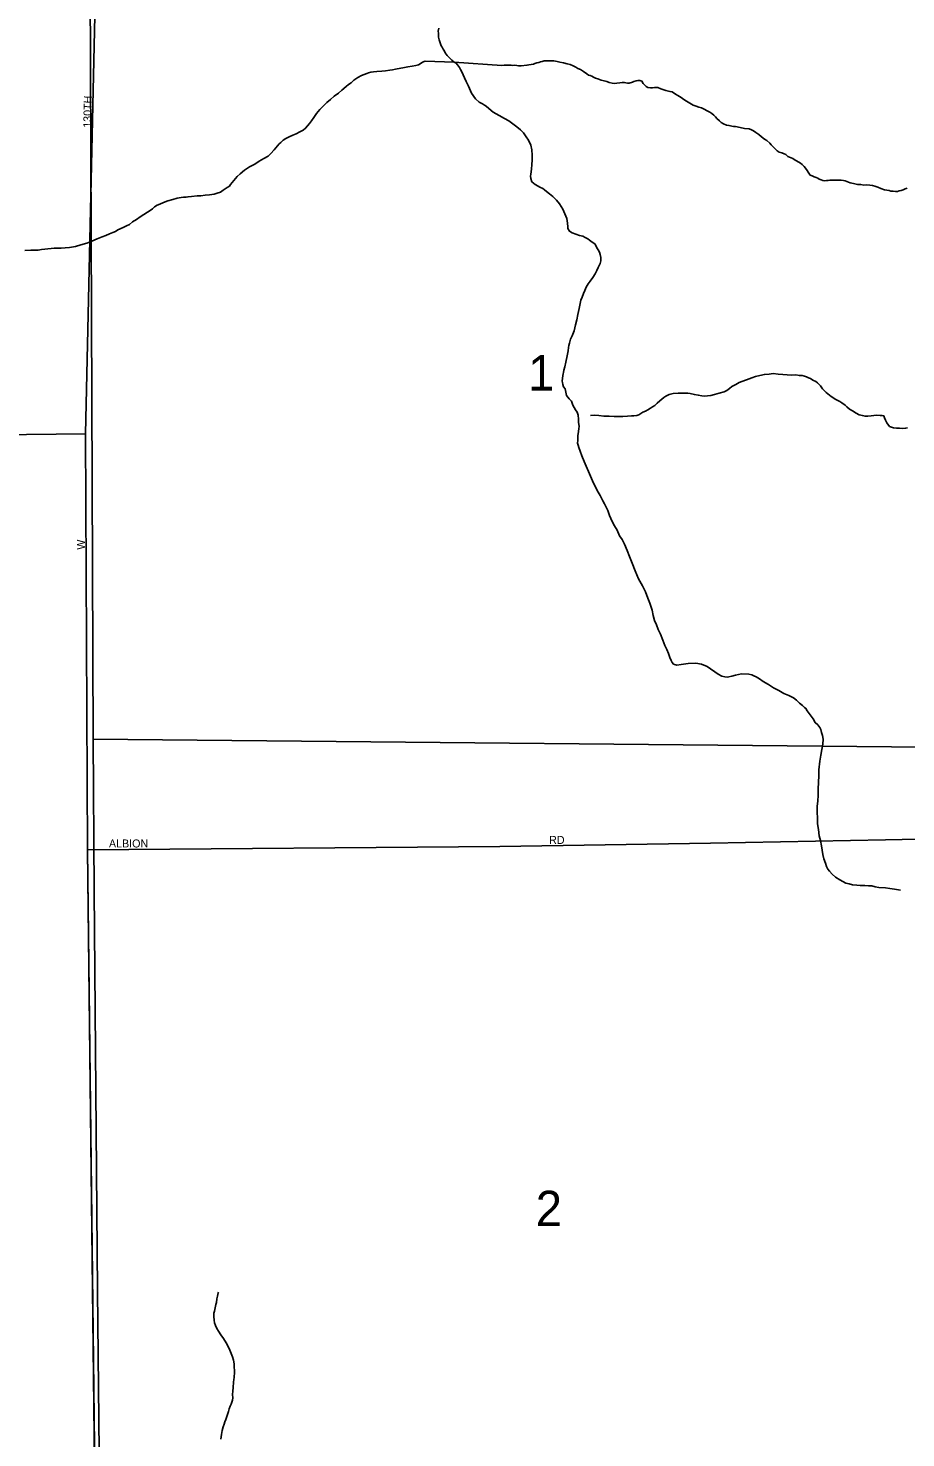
# Model space of a CAD drawing. Extents: x 2010165 to 2382125, y 1060529 to 1407316.
# Drawn here: x 2164475 to 2169958, y 1212363 to 1221171 of the extents above; entities that cross this region are included whole.
import ezdxf

# ---------------------------------------------------------------- set-up
doc = ezdxf.new("R2010")
doc.units = 0
for name, color, linetype in [('GM_X_City_Street', 7, 'Continuous'), ('GM_X_City_Street_Text', 7, 'Continuous'), ('GM_X_Corporation', 7, 'Continuous'), ('GM_X_Minor_River', 7, 'Continuous'), ('GM_X_Section', 7, 'Continuous'), ('GM_X_Section_Text', 7, 'Continuous')]:
    doc.layers.add(name, color=color, linetype=linetype)

msp = doc.modelspace()

# ---------------------------------------------------------------- linework, layer by layer
at = {"layer": 'GM_X_City_Street'}
for points in [[(2164931.2, 1207965.8), (2164930.1, 1208081.5), (2164898.5, 1211429), (2164897.7, 1211462), (2164844.7, 1216037.6), (2164832.8, 1218637), (2164895.8, 1221436.7)], [(2156588.9, 1218553.8), (2158477.6, 1218575.9), (2160599.4, 1218587.6), (2164832.8, 1218637)], [(2164844.7, 1216037.6), (2167420.4, 1216057.6), (2168738.1, 1216077.8), (2169831.9, 1216100.1), (2172347.5, 1216149.6)]]:
    msp.add_lwpolyline(points, dxfattribs=at)
at = {"layer": 'GM_X_Corporation'}
for points in [[(2186878.7, 1221701), (2186923.4, 1220744.1), (2186933.5, 1220238.7), (2186941.3, 1219753.4), (2186978.3, 1216841.2), (2187013.9, 1213879), (2187027.1, 1208132.6), (2187205, 1194725.9), (2177123.5, 1194567.9), (2176176.5, 1194580.3), (2174206.9, 1194531), (2167776.4, 1194381.4), (2165054.7, 1194304.8), (2164968.9, 1199659.4), (2164935.2, 1207756.2), (2164931.8, 1207897.8), (2164930.1, 1208081.5), (2164898.5, 1211429), (2164844.7, 1216037.6), (2164832.8, 1218637), (2164895.8, 1221436.7)], [(2164895.8, 1221436.7), (2164832.8, 1218637), (2164844.7, 1216037.6), (2164898.5, 1211429), (2164930.1, 1208081.5), (2164931.8, 1207897.8), (2164935.2, 1207756.2), (2164968.9, 1199659.4), (2165054.7, 1194304.8), (2162687.3, 1194296.8), (2162163.4, 1194282.6), (2161645.6, 1194276.5), (2161453.7, 1194270.4), (2159224.5, 1194187.1), (2158831.1, 1194172.4), (2158006.9, 1194141.9), (2154020.1, 1193994.5), (2151351.3, 1193919.5)]]:
    msp.add_lwpolyline(points, dxfattribs=at)
at = {"layer": 'GM_X_Minor_River'}
for points in [[(2167040.7, 1221172), (2167037, 1221151.9), (2167037.1, 1221139.9), (2167037.2, 1221129.8), (2167037.4, 1221115.8), (2167041.7, 1221097.8), (2167047.9, 1221079.8), (2167054.2, 1221061.8), (2167060.3, 1221051.9), (2167066.5, 1221039.9), (2167074.6, 1221028), (2167080.8, 1221018), (2167093, 1221000.1), (2167109.3, 1220984.2), (2167121.4, 1220972.3), (2167135.7, 1220958.5), (2167147.7, 1220952.6), (2167155.9, 1220942.7), (2167170.2, 1220924.8), (2167176.3, 1220912.8), (2167182.5, 1220902.9), (2167211.3, 1220839), (2167225.8, 1220809.1), (2167244.4, 1220765.2), (2167268.9, 1220729.4), (2167293.2, 1220709.6), (2167313.4, 1220697.8), (2167325.5, 1220689.9), (2167335.6, 1220684), (2167351.8, 1220670.2), (2167380.1, 1220646.4), (2167416.5, 1220624.8), (2167450.8, 1220607.2), (2167477, 1220591.4), (2167503.3, 1220573.7), (2167527.6, 1220553.9), (2167549.9, 1220536.2), (2167568.2, 1220516.3), (2167586.5, 1220492.5), (2167600.8, 1220470.6), (2167615.2, 1220440.7), (2167621.6, 1220410.6), (2167624.1, 1220378.6), (2167622.5, 1220348.4), (2167620.8, 1220318.3), (2167619.2, 1220292.2), (2167617.4, 1220274.1), (2167615.6, 1220258.1), (2167613.8, 1220246), (2167616, 1220232), (2167622.2, 1220212), (2167642.5, 1220194.2), (2167660.7, 1220184.4), (2167670.8, 1220178.5), (2167690.9, 1220168.7), (2167701, 1220160.8), (2167713.2, 1220150.9), (2167731.4, 1220137.1), (2167751.7, 1220119.3), (2167776, 1220097.5), (2167794.3, 1220073.6), (2167814.8, 1220039.8), (2167827.2, 1220011.8), (2167839.6, 1219981.9), (2167844, 1219951.9), (2167846.3, 1219929.8), (2167846.4, 1219919.8), (2167856.7, 1219901.9), (2167872.8, 1219892), (2167897, 1219884.3), (2167919.1, 1219876.5), (2167939.2, 1219870.8), (2167955.4, 1219862.9), (2167971.5, 1219855.1), (2167981.6, 1219847.2), (2167997.8, 1219833.4), (2168014, 1219823.5), (2168022.1, 1219813.6), (2168028.3, 1219799.6), (2168036.5, 1219785.7), (2168044.7, 1219771.7), (2168048.9, 1219757.7), (2168053.2, 1219737.7), (2168051.4, 1219717.6), (2168047.6, 1219701.5)], [(2166052.3, 1220457.6), (2166068.1, 1220471.9), (2166084, 1220482.1), (2166105.9, 1220492.4), (2166127.8, 1220502.7), (2166147.8, 1220511), (2166171.6, 1220523.3), (2166193.5, 1220533.6), (2166207.4, 1220545.8), (2166219.2, 1220560), (2166233.1, 1220576.2), (2166244.9, 1220592.4), (2166258.6, 1220612.7), (2166276.3, 1220637), (2166296, 1220663.3), (2166319.8, 1220685.6), (2166339.5, 1220706), (2166363.3, 1220726.3), (2166387.1, 1220746.7), (2166412.9, 1220765), (2166434.7, 1220783.4), (2166460.5, 1220805.8), (2166476.3, 1220820), (2166492.2, 1220830.2), (2166510, 1220846.5), (2166533.8, 1220862.8), (2166557.7, 1220875.2), (2166573.7, 1220881.4), (2166589.6, 1220887.6), (2166601.6, 1220891.8), (2166615.6, 1220895.9), (2166631.6, 1220898.1), (2166653.6, 1220900.4), (2166683.6, 1220902.8), (2166707.6, 1220905.1), (2166733.6, 1220909.4), (2166751.6, 1220911.6), (2166769.6, 1220915.9), (2166825.5, 1220924.6), (2166847.5, 1220928.9), (2166873.5, 1220933.2), (2166895.5, 1220937.5), (2166913.5, 1220941.7), (2166923.4, 1220947.9), (2166937.3, 1220958.1), (2166955.3, 1220964.3), (2167135, 1220959.1)], [(2167135, 1220959.1), (2167434.4, 1220938.1), (2167448.4, 1220940.2), (2167466.5, 1220940.4), (2167478.5, 1220940.6), (2167490.5, 1220940.8), (2167500.5, 1220938.9), (2167512.6, 1220939), (2167526.6, 1220937.2), (2167538.7, 1220935.3), (2167554.7, 1220935.5), (2167590.7, 1220940), (2167602.7, 1220942.1), (2167616.7, 1220944.3), (2167630.7, 1220946.5), (2167640.6, 1220950.6), (2167652.6, 1220954.8), (2167664.6, 1220956.9), (2167674.6, 1220961.1), (2167686.6, 1220963.2), (2167698.5, 1220967.4), (2167712.5, 1220967.5), (2167722.6, 1220967.7), (2167736.6, 1220967.8), (2167758.6, 1220966.1), (2167778.7, 1220962.3), (2167796.8, 1220958.5), (2167818.9, 1220954.8), (2167841, 1220949.1), (2167861.1, 1220943.3), (2167879.3, 1220935.5), (2167895.4, 1220927.6), (2167909.5, 1220919.8), (2167925.6, 1220912), (2167943.8, 1220900.1), (2167964, 1220886.3), (2167976.2, 1220878.5), (2167986.2, 1220874.6), (2167996.3, 1220870.7), (2168006.4, 1220864.8), (2168018.5, 1220858.9), (2168032.6, 1220855.1), (2168044.6, 1220851.2), (2168054.7, 1220847.3), (2168072.8, 1220841.5), (2168088.9, 1220837.7), (2168105, 1220831.9), (2168123.1, 1220828.1), (2168137.1, 1220826.3), (2168153.1, 1220828.5), (2168171.2, 1220828.7), (2168185.2, 1220830.9), (2168199.2, 1220831), (2168209.2, 1220829.1), (2168219.3, 1220827.3), (2168229.3, 1220827.4), (2168249.2, 1220833.7), (2168259.2, 1220837.8), (2168273.2, 1220842), (2168283.2, 1220844.1), (2168295.2, 1220844.2), (2168309.2, 1220840.4), (2168317.4, 1220826.5), (2168335.7, 1220806.6), (2168345.8, 1220800.7), (2168361.9, 1220798.9), (2168375.9, 1220799.1), (2168387.9, 1220801.2), (2168408, 1220799.5), (2168428.1, 1220791.7), (2168458.3, 1220782), (2168484.4, 1220776.3), (2168498.5, 1220772.5), (2168518.7, 1220758.7), (2168532.8, 1220750.8), (2168542.9, 1220744.9), (2168555, 1220737.1), (2168571.2, 1220725.2), (2168587.4, 1220715.4), (2168629.8, 1220689.8), (2168647.9, 1220684), (2168664, 1220678.2), (2168682.1, 1220672.4), (2168698.2, 1220664.6), (2168716.4, 1220654.8), (2168732.5, 1220646.9), (2168746.7, 1220637.1), (2168758.8, 1220627.2), (2168769, 1220617.3), (2168777.1, 1220607.4), (2168793.3, 1220591.5), (2168803.5, 1220581.6), (2168819.6, 1220573.8), (2168837.7, 1220566), (2168853.8, 1220562.1), (2168869.9, 1220558.3)], [(2168869.9, 1220558.3), (2168881.9, 1220556.5), (2168894, 1220556.6), (2168922.1, 1220550.9), (2168950.2, 1220545.3), (2168978.3, 1220541.6), (2168994.4, 1220535.8), (2169006.5, 1220529.9), (2169020.7, 1220520), (2169038.9, 1220506.2), (2169057.1, 1220492.4), (2169075.3, 1220478.6), (2169089.5, 1220468.7), (2169107.7, 1220452.9), (2169115.8, 1220442.9), (2169130, 1220429.1), (2169140.2, 1220419.2), (2169154.4, 1220405.3), (2169166.5, 1220397.4), (2169182.6, 1220391.6), (2169198.7, 1220385.8), (2169208.8, 1220381.9), (2169221, 1220370), (2169241.1, 1220360.2), (2169251.2, 1220356.3), (2169261.3, 1220350.4), (2169299.7, 1220326.8), (2169309.8, 1220318.9), (2169322, 1220307), (2169332.1, 1220297.1), (2169342.4, 1220281.2), (2169348.5, 1220271.2), (2169360.7, 1220253.3), (2169372.8, 1220247.5), (2169384.9, 1220241.6), (2169397, 1220237.7), (2169407.1, 1220233.8), (2169417.2, 1220227.9), (2169429.2, 1220224.1), (2169439.3, 1220220.2), (2169451.4, 1220218.3), (2169461.4, 1220218.4), (2169471.4, 1220218.6), (2169483.4, 1220220.7), (2169493.4, 1220220.8), (2169513.4, 1220221.1), (2169525.4, 1220221.2), (2169537.5, 1220221.4), (2169553.5, 1220221.6), (2169567.5, 1220219.7), (2169579.6, 1220217.9), (2169589.7, 1220214), (2169609.8, 1220204.2), (2169631.9, 1220200.5), (2169656, 1220194.7), (2169676.1, 1220195), (2169696.1, 1220191.2), (2169714.2, 1220191.4), (2169732.2, 1220189.6), (2169750.3, 1220187.9), (2169764.4, 1220184), (2169782.5, 1220178.2), (2169802.6, 1220170.4), (2169824.8, 1220160.7), (2169852.9, 1220157), (2169864.9, 1220153.1), (2169879, 1220153.3), (2169893, 1220151.5), (2169905, 1220151.6), (2169917, 1220153.8), (2169929, 1220157.9), (2169941, 1220160.1), (2169952.9, 1220168.3), (2169966.9, 1220172.5)], [(2164454.3, 1219782), (2164490.3, 1219784.4), (2164514.4, 1219784.7), (2164536.4, 1219785), (2164558.4, 1219787.3), (2164578.4, 1219789.5), (2164636.4, 1219796.3), (2164656.5, 1219796.5), (2164680.5, 1219796.8), (2164706.5, 1219799.1), (2164732.5, 1219801.4), (2164770.5, 1219807.9), (2164804.5, 1219816.4), (2164840.4, 1219826.8), (2164872.3, 1219841.3), (2164906.1, 1219855.7), (2164936, 1219868.1), (2164960, 1219876.5), (2164981.9, 1219886.8), (2165003.8, 1219895.1), (2165019.7, 1219901.3), (2165035.6, 1219911.5), (2165067.5, 1219925.9), (2165089.4, 1219936.2), (2165107.3, 1219944.5), (2165127.1, 1219960.8), (2165151, 1219975.1), (2165174.8, 1219991.5), (2165196.7, 1220007.8), (2165220.5, 1220022.1), (2165236.4, 1220032.3), (2165250.3, 1220042.5), (2165264.2, 1220054.8), (2165280.1, 1220065), (2165298, 1220071.2), (2165319.9, 1220081.5), (2165347.8, 1220091.9), (2165377.8, 1220100.3), (2165405.7, 1220108.6), (2165429.7, 1220112.9), (2165445.7, 1220115.1), (2165461.7, 1220115.3), (2165473.7, 1220117.5), (2165495.7, 1220119.8), (2165529.7, 1220124.2), (2165553.8, 1220124.5), (2165579.8, 1220126.8), (2165607.8, 1220129.2), (2165635.8, 1220133.5), (2165655.7, 1220139.8), (2165675.7, 1220146.1), (2165693.6, 1220158.3), (2165717.4, 1220174.6), (2165731.3, 1220184.9), (2165739.2, 1220195), (2165780.6, 1220243.6), (2165798.4, 1220261.9), (2165826.1, 1220284.3), (2165857.9, 1220304.8), (2165889.8, 1220321.2), (2165917.6, 1220339.6), (2165947.4, 1220356), (2165973.3, 1220372.4), (2165991.1, 1220388.7), (2166010.8, 1220411), (2166032.5, 1220435.3), (2166042.4, 1220447.5), (2166052.3, 1220457.6)], [(2168047.6, 1219701.5), (2168041.8, 1219687.4), (2168036, 1219675.3), (2168028.2, 1219657.2), (2168016.4, 1219636.9), (2168002.7, 1219612.7), (2167985, 1219590.4), (2167973.2, 1219574.2), (2167961.4, 1219552), (2167951.7, 1219531.8), (2167943.9, 1219513.7), (2167936.2, 1219489.5), (2167928.4, 1219471.3), (2167922.7, 1219451.2), (2167917.1, 1219419), (2167909.6, 1219382.8), (2167902, 1219348.6), (2167894.4, 1219318.4), (2167884.8, 1219280.2), (2167873.2, 1219248), (2167863.5, 1219227.8), (2167855.8, 1219203.6), (2167852, 1219187.5), (2167850.1, 1219175.4), (2167848.4, 1219155.3), (2167842.8, 1219123.2), (2167833.3, 1219084.9), (2167827.7, 1219054.8), (2167821.9, 1219034.6), (2167820.1, 1219020.6), (2167816.2, 1219010.5), (2167814.4, 1219000.4), (2167810.8, 1218966.3), (2167812.9, 1218956.3), (2167815.1, 1218944.3), (2167819.3, 1218930.3), (2167829.5, 1218918.4), (2167838, 1218876.3), (2167854.3, 1218854.5), (2167868.5, 1218840.6), (2167876.9, 1218816.6), (2167885.1, 1218800.6), (2167893.3, 1218786.7), (2167903.5, 1218770.8), (2167909.8, 1218752.8), (2167912.1, 1218728.8), (2167912.4, 1218706.7), (2167914.5, 1218696.7), (2167916.7, 1218682.7), (2167914.9, 1218670.6), (2167913.1, 1218650.5), (2167909.4, 1218624.4), (2167907.8, 1218594.3), (2167906, 1218578.2), (2167910.2, 1218566.2), (2167914.4, 1218550.2), (2167922.7, 1218528.2), (2167933.1, 1218498.3), (2167947.6, 1218464.3), (2167986.9, 1218372.5), (2168001.3, 1218342.6), (2168015.7, 1218310.7), (2168036.2, 1218272.8), (2168048.6, 1218250.9), (2168056.8, 1218234.9), (2168065, 1218217), (2168075.3, 1218199), (2168085.6, 1218179.1), (2168095.9, 1218157.1), (2168106.3, 1218125.2), (2168122.8, 1218089.3), (2168137.2, 1218061.3), (2168153.6, 1218033.5), (2168168, 1217999.5), (2168186.4, 1217975.7), (2168200.8, 1217947.8), (2168217.3, 1217907.8), (2168231.8, 1217869.9), (2168248.4, 1217828), (2168267.1, 1217780), (2168287.8, 1217730.1), (2168312.4, 1217686.3), (2168330.9, 1217648.4), (2168345.4, 1217610.4), (2168357.9, 1217578.5), (2168372.5, 1217534.5), (2168378.9, 1217500.5), (2168387.3, 1217470.5), (2168399.7, 1217442.6), (2168410.1, 1217414.6), (2168424.5, 1217384.7), (2168439, 1217346.7), (2168451.5, 1217314.8), (2168463.8, 1217288.9), (2168474.2, 1217262.9), (2168482.5, 1217238.9), (2168490.8, 1217221), (2168499, 1217207), (2168507.1, 1217197.1), (2168527.2, 1217191.3), (2168555.2, 1217195.7)], [(2167987.9, 1218751.8), (2168011.9, 1218752.1), (2168040, 1218750.4), (2168070.1, 1218746.7), (2168104.2, 1218747.1), (2168136.3, 1218745.5), (2168164.3, 1218743.9), (2168190.4, 1218744.2), (2168218.4, 1218746.6), (2168244.4, 1218748.9), (2168258.4, 1218749), (2168276.4, 1218751.3), (2168290.4, 1218755.4), (2168314.2, 1218771.8), (2168332.2, 1218778), (2168346.1, 1218786.2), (2168362, 1218796.5), (2168375.9, 1218804.7), (2168389.8, 1218812.8), (2168403.6, 1218829.1), (2168421.5, 1218843.3), (2168433.4, 1218853.5), (2168445.3, 1218863.7), (2168459.2, 1218871.9), (2168479.1, 1218882.2), (2168505, 1218888.5), (2168535.1, 1218890.9), (2168563.1, 1218891.2), (2168583.1, 1218891.5), (2168595.2, 1218889.6), (2168611.2, 1218887.8), (2168637.4, 1218882.1), (2168661.4, 1218878.4), (2168683.5, 1218874.6), (2168701.6, 1218872.8), (2168719.6, 1218873.1), (2168739.6, 1218875.3), (2168761.6, 1218881.6), (2168791.5, 1218890), (2168823.5, 1218898.4), (2168839.4, 1218906.6), (2168855.2, 1218918.9), (2168871.1, 1218933.1), (2168895, 1218945.4), (2168916.9, 1218957.7), (2168978.7, 1218980.6), (2168996.6, 1218986.8), (2169018.5, 1218995.1), (2169046.5, 1219001.5), (2169074.5, 1219007.8), (2169104.5, 1219010.2), (2169128.5, 1219012.5), (2169160.6, 1219008.9), (2169188.7, 1219007.2), (2169216.8, 1219005.6), (2169242.8, 1219003.9), (2169270.9, 1219004.2), (2169293, 1219000.5), (2169311, 1219000.7), (2169325.1, 1218996.8), (2169337.1, 1218993), (2169349.2, 1218987.1), (2169363.3, 1218981.3), (2169377.5, 1218971.4), (2169395.6, 1218963.6), (2169405.7, 1218955.7), (2169413.9, 1218945.8), (2169424, 1218935.9), (2169438.3, 1218918), (2169460.6, 1218894.2), (2169491, 1218870.5), (2169521.3, 1218850.8), (2169545.5, 1218839), (2169557.6, 1218831.1), (2169577.9, 1218815.3), (2169590, 1218805.5), (2169606.2, 1218791.6), (2169624.4, 1218779.8), (2169646.6, 1218766), (2169666.8, 1218756.2), (2169686.9, 1218750.5), (2169703, 1218746.6), (2169721, 1218746.9), (2169741, 1218749.1), (2169759, 1218751.3), (2169777, 1218753.6), (2169797.1, 1218751.8), (2169811.1, 1218750), (2169821.2, 1218748.1), (2169825.3, 1218736.1), (2169831.5, 1218722.1), (2169839.8, 1218704.2), (2169856.1, 1218682.3), (2169880.2, 1218674.6), (2169900.3, 1218672.8), (2169918.3, 1218671), (2169936.4, 1218669.2), (2169956.4, 1218671.5), (2169968.4, 1218673.6)], [(2168555.2, 1217195.7), (2168597.2, 1217202.2), (2168645.3, 1217202.8), (2168681.4, 1217197.2), (2168717.6, 1217183.6), (2168786.4, 1217134.3), (2168808.6, 1217122.5), (2168826.7, 1217118.7), (2168840.7, 1217116.9), (2168852.7, 1217119.1), (2168870.7, 1217121.3), (2168894.7, 1217127.6), (2168930.6, 1217136.1), (2168976.7, 1217134.6), (2168996.8, 1217130.8), (2169008.9, 1217125), (2169023, 1217117.1), (2169043.2, 1217105.3), (2169067.5, 1217089.6), (2169099.8, 1217069.9), (2169132.1, 1217050.2), (2169164.4, 1217032.6), (2169196.7, 1217014.9), (2169226.9, 1217001.2), (2169257.1, 1216987.6), (2169275.4, 1216971.7), (2169293.6, 1216953.9), (2169311.9, 1216938.1), (2169324.1, 1216926.2), (2169334.1, 1216920.3), (2169342.3, 1216906.3), (2169354.6, 1216888.4), (2169366.8, 1216872.5), (2169379.1, 1216856.6), (2169391.4, 1216832.7), (2169407.6, 1216818.8), (2169419.9, 1216800.9), (2169426, 1216789), (2169430.3, 1216771), (2169436.5, 1216751), (2169440.8, 1216729), (2169439.2, 1216696.8), (2169433.7, 1216664.7), (2169426.1, 1216628.5), (2169420.6, 1216590.3), (2169415.3, 1216538), (2169413.7, 1216501.9), (2169412.3, 1216457.8), (2169410.8, 1216417.6), (2169409.4, 1216377.4), (2169407.8, 1216343.3), (2169404.3, 1216307.2), (2169405.7, 1216198.8), (2169412.1, 1216164.8), (2169416.7, 1216124.7), (2169425.1, 1216094.7), (2169431.5, 1216062.7), (2169435.9, 1216034.7), (2169440.2, 1216008.6), (2169446.6, 1215980.6), (2169455, 1215954.7), (2169463.3, 1215932.7), (2169471.5, 1215916.7), (2169481.7, 1215902.8), (2169497.9, 1215885), (2169518.2, 1215867.1), (2169546.5, 1215849.4), (2169564.6, 1215839.6), (2169582.8, 1215829.8), (2169602.9, 1215824), (2169625, 1215818.3), (2169651.1, 1215816.6), (2169673.2, 1215814.9), (2169701.2, 1215813.2), (2169725.3, 1215811.5), (2169745.3, 1215811.7), (2169765.4, 1215806), (2169789.5, 1215802.2), (2169831.6, 1215798.8), (2169857.7, 1215795.1), (2169887.8, 1215791.4), (2169924, 1215785.8), (2169924.7, 1215785.8)], [(2165677.4, 1212355.3), (2165683, 1212383.5), (2165686.7, 1212409.6), (2165692.4, 1212431.7), (2165698.2, 1212447.8), (2165704, 1212462), (2165709.9, 1212478.1), (2165719.5, 1212508.3), (2165725.2, 1212528.4), (2165731, 1212544.5), (2165736.8, 1212560.7), (2165742.7, 1212572.8), (2165746.5, 1212586.9), (2165750.3, 1212598.9), (2165752.2, 1212613), (2165751.9, 1212633.1), (2165753.6, 1212655.2), (2165755.3, 1212677.2), (2165756.9, 1212711.4), (2165758.7, 1212727.4), (2165762.5, 1212739.5), (2165762.4, 1212749.6), (2165764.2, 1212763.6), (2165761.4, 1212825.8), (2165757.1, 1212847.8), (2165750.8, 1212869.8), (2165742.5, 1212889.8), (2165734.2, 1212911.7), (2165723.9, 1212933.7), (2165711.6, 1212955.6), (2165695.2, 1212983.5), (2165678.9, 1213007.3), (2165664.6, 1213029.2), (2165652.3, 1213047.2), (2165644.1, 1213065.1), (2165637.8, 1213081.1), (2165635.6, 1213099.1), (2165635.3, 1213121.2), (2165635.1, 1213141.2), (2165638.9, 1213155.3), (2165642.6, 1213175.4), (2165646.4, 1213195.5), (2165650.2, 1213209.6), (2165653.9, 1213231.8), (2165657.7, 1213247.8), (2165659.6, 1213257.9), (2165661.4, 1213270), (2165663.4, 1213274)]]:
    msp.add_lwpolyline(points, dxfattribs=at)
at = {"layer": 'GM_X_Section'}
for points in [[(2168586.2, 1221473.3), (2170463.9, 1221481), (2170517.3, 1216673.9), (2164881.3, 1216727.8), (2164874, 1218333.8), (2164860.8, 1221446.2)], [(2170517.3, 1216673.9), (2170583.9, 1211012.5), (2164931.4, 1211072.2), (2164907.3, 1213281.5), (2164886.2, 1215783.6), (2164881.3, 1216727.8)]]:
    msp.add_lwpolyline(points, close=True, dxfattribs=at)

# ---------------------------------------------------------------- texts
at = {"layer": 'GM_X_City_Street_Text'}
for s, rotation, p in [('130TH', 88.83149, (2164868.4, 1220548.2)), ('W', 90, (2164828.9, 1217912.4)), ('RD', 0.00001, (2167729.1, 1216073.8)), ('ALBION', 0.00001, (2164979.1, 1216051.8))]:
    msp.add_text(s, height=50, rotation=rotation, dxfattribs=at).set_placement(p)
at = {"layer": 'GM_X_Section_Text'}
for s, p in [('1', (2167597, 1218907.1)), ('2', (2167645.5, 1213686))]:
    msp.add_text(s, height=221, rotation=0.00001, dxfattribs=at).set_placement(p)

doc.saveas('drawing.dxf')
